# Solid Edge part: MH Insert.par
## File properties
Author: Dave
Template: Normal.par
Last saved by: Dave
Revision: 15
Application: Solid Edge
Accuracy: 0.990
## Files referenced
..\Mould Assy.asm
EC:\drawings\DK laminates\Squared Leg Foot\ToolDrawings\Mould Assy.asm
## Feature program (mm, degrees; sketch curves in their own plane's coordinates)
sketch for "unnamed Protrusion 1" plane through (0, 0, 0) normal (0, 0, 1) x-axis (1, 0, 0)
  line (-16.0172, 29.4336) -> (-29.448, 15.9987)
  line (-29.448, 15.9987) -> (-29.4408, -29.4501)
  line (-29.4408, -29.4501) -> (29.4408, -29.4408)
  line (29.4408, -29.4408) -> (29.4315, 29.4408)
  line (29.4315, 29.4408) -> (-16.0172, 29.4336)
extrude "unnamed Protrusion 1" add finite 36 along +normal
boolean "unnamed Boolean 1"
sketch for "Hole_5" plane through (-5.5904, 5.5794, 33.476) normal (0, 0, 1) x-axis (1, 0.000158, 0)
  hole centre (23.6751, -1.8251) bore radius 1.25
hole "Hole_5" diameter 2.5 through  VBottomAngle = 118 deg
sketch for "unnamed Hole 1" plane through (-5.5904, 5.5794, 33.476) normal (0, 0, 1) x-axis (1, 0.000158, 0)
  hole centre (7.9251, 19.8749) bore radius 1.25
hole "unnamed Hole 1" through
sketch for "unnamed Hole 2" plane through (-5.5904, 5.5794, 33.476) normal (0, 0, 1) x-axis (1, 0.000158, 0)
  hole centre (-19.8749, -7.9251) bore radius 1.25
hole "unnamed Hole 2" through
sketch for "unnamed Hole 3" plane through (-5.5904, 5.5794, 33.476) normal (0, 0, 1) x-axis (1, 0.000158, 0)
  hole centre (1.8251, -23.6751) bore radius 1.25
hole "unnamed Hole 3" through
sketch for "Hole_9" plane through (-0.0036, -0.0046, 0) normal (0, 0, -1) x-axis (-1, -0.000158, 0)
  hole centre (-23.4621, -23.4408) bore radius 2.4585
hole "Hole_9" finite  VBottomAngle = 118 deg; ThreadDepth = 10 mm
sketch for "unnamed Hole 4" plane through (-0.0036, -0.0046, 0) normal (0, 0, -1) x-axis (-1, -0.000158, 0)
  hole centre (23.4419, -23.4408) bore radius 2.4585
hole "unnamed Hole 4" finite
sketch for "unnamed Hole 5" plane through (-0.0036, -0.0046, 0) normal (0, 0, -1) x-axis (-1, -0.000158, 0)
  hole centre (-23.4621, 23.4408) bore radius 2.4585
hole "unnamed Hole 5" finite
sketch for "Hole_13" plane through (-3.765, 3.7546, 36) normal (0, 0, 1) x-axis (0, 1, 0)
  hole centre (0, 0) bore radius 5
hole "Hole_13" diameter 10 through  VBottomAngle = 118 deg
sketch for "Hole_14" plane through (-0.0036, -0.0046, 0) normal (0, 0, -1) x-axis (0.000158, -1, 0)
hole "Hole_14" diameter 5 finite
pattern "unnamed Pattern 1" of "Hole_14"
sketch for "Hole_18" plane through (-29.4444, -6.7257, 15.226) normal (-1, -0.000158, 0) x-axis (0.000158, -1, 0)
hole "Hole_18" diameter 5 finite
sketch for "Hole_22" plane through (-29.4444, -6.7257, 15.226) normal (-1, -0.000158, 0) x-axis (0.000158, -1, 0)
hole "Hole_22" diameter 5 finite  VBottomAngle = 118 deg
sketch for "Hole_23" plane through (-0.0036, -0.0046, 0) normal (0, 0, -1) x-axis (0.000158, -1, 0)
hole "Hole_23" diameter 5 finite  VBottomAngle = 118 deg
sketch for "Hole_24" plane through (0, -29.4454, 10.69) normal (0.000158, -1, 0) x-axis (1, 0.000158, 0)
hole "Hole_24" diameter 5 finite  VBottomAngle = 118 deg
sketch for "Hole_25" plane through (-0.0036, -0.0046, 0) normal (0, 0, -1) x-axis (-1, -0.000158, 0)
hole "Hole_25" diameter 9 finite
sketch for "unnamed Hole 6" plane through (-0.0036, -0.0046, 0) normal (0, 0, -1) x-axis (-1, -0.000158, 0)
hole "unnamed Hole 6" finite
pattern "unnamed Pattern 2" of "Hole_25", "unnamed Hole 6"
pattern "unnamed Pattern 3" of "Hole_5", "unnamed Hole 1", "unnamed Hole 2", "unnamed Hole 3"
pattern "unnamed Pattern 4" of "Hole_9", "unnamed Hole 4", "unnamed Hole 5"
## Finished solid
Body 1: solid body, 252 faces, 528 edges, 282 vertices.
  Faces by surface: cylinder 102, spline 48, plane 43, sphere 38, torus 16, cone 5
  Edges by curve: line 200, circle 168, curve on surface 124, ellipse 26, spline 10
Body 2: solid body, 181 faces, 379 edges, 199 vertices.
  Faces by surface: cylinder 70, plane 35, spline 31, sphere 19, cone 14, torus 12
  Edges by curve: circle 128, line 121, curve on surface 75, ellipse 32, intersection 15, spline 8
Bounding box of the edges (mm; curved faces can reach further): 61.697 x 61.699 x 61.700, from (-30.852, -30.8542, 0) to (30.8449, 30.8449, 61.7).
Cylindrical faces by radius (mm): R0.504 x145, R1.008 x4, R1.25 x4, R2.4585 x3, R2.5 x10, R4.2235 x1, R4.5 x2, R5 x1, R7.2475 x2
Conical faces (half-angle, radius in mm at the cone's reference point): 1 deg R7.056 x1, 1 deg R20.412 x2, 1 deg R23.436 x6, 59 deg R2.4585 x3, 59 deg R2.5 x7
Toroidal faces (ring radius, tube radius in mm): R0.504 r0.504 x3, R1.512 r0.504 x1, R6.1209 r0.504 x1, R6.7435 r0.504 x2, R7.5513 r0.504 x1, R7.7515 r0.504 x2, R19.9167 r0.504 x2, R21.1184 r0.504 x4, R22.7296 r0.504 x6, R23.9313 r0.504 x6
Spherical faces by radius (mm): R0.504 x57
Planar faces by outward normal: +x 3, +y 2, +z 10, -x 3, -y 3, -z 12, oblique 45
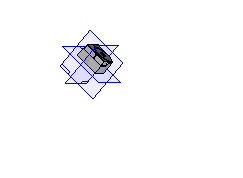
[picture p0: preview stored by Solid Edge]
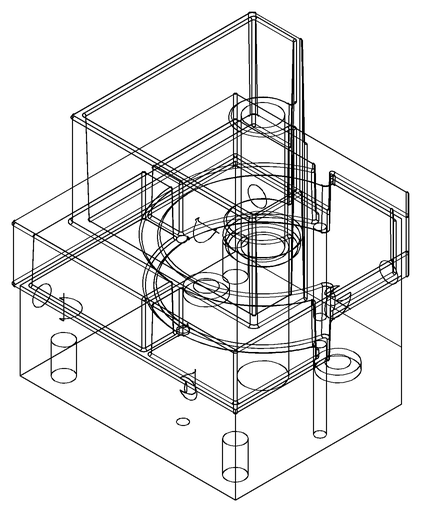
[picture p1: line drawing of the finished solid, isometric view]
